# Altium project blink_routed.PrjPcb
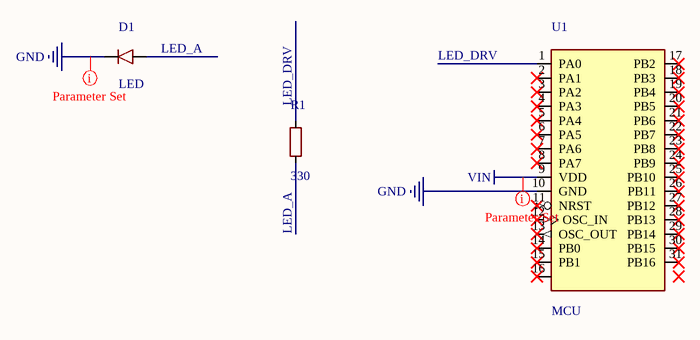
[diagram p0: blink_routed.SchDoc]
1 sheet, 3 parts. Net scope: global (net labels, ports and power ports of the same name join across sheets).
Board file: blink_routed.PcbDoc

## Sheet blink_routed.SchDoc
size A4

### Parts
D1  LED  [Mini_LED_THT_3mm]
R1  330  [Mini_R_0603]
U1  MCU  [Mini_QFP-32_7x7mm_P0.8mm]

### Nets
GND: D1.1(K) U1.10(GND)
VIN: U1.9(VDD)
LED_A: D1.2(A) R1.2
LED_DRV: R1.1 U1.1(PA0)

Not connected (* = marked no-connect by the designer): U1 2(PA1)* 3(PA2)* 4(PA3)* 5(PA4)* 6(PA5)* 7(PA6)* 8(PA7)* 11(NRST)* 12(OSC_IN)* 13(OSC_OUT)* 14(PB0)* 15(PB1)* 16* 17(PB2)* 18(PB3)* 19(PB4)* 20(PB5)* 21(PB6)* 22(PB7)* 23(PB8)* 24(PB9)* 25(PB10)* 26(PB11)* 27(PB12)* 28(PB13)* 29(PB14)* 30(PB15)* 31(PB16)* 32(EP)

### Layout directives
net class PWR: GND, VIN

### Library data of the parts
D1 = Mini_LED
R1 = Mini_R
U1 = Mini_QFP32_IC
